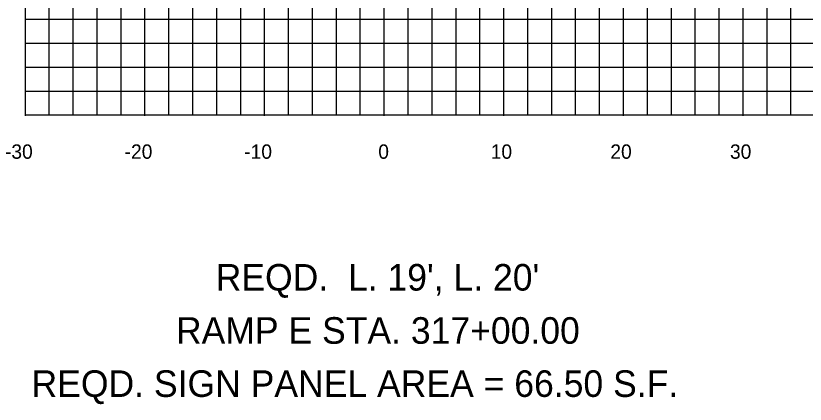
# Model space of a CAD drawing. Extents: x 2193008 to 2198143, y 1236112 to 1237864.
# Drawn here: x 2195238 to 2195304, y 1237233.9 to 1237266.4 of the extents above; entities that cross this region are included whole.
import ezdxf

# ---------------------------------------------------------------- set-up
doc = ezdxf.new("R2010")
doc.units = 0
for name, color, linetype in [('60', 7, 'Continuous'), ('Level 55', 7, 'Continuous'), ('LIMT-CSLINE', 7, 'Continuous'), ('M-ROADS', 7, 'Continuous')]:
    doc.layers.add(name, color=color, linetype=linetype)

msp = doc.modelspace()

# ---------------------------------------------------------------- linework, layer by layer
at = {"layer": '60'}
for p, q in [((2195238.783, 1237258.106), (2195238.783, 1237318.106)), ((2195238.783, 1237258.046), (2195238.783, 1237258.106)), ((2195238.783, 1237258.106), (2195368.783, 1237258.106)), ((2195248.783, 1237258.046), (2195248.783, 1237258.106)), ((2195258.783, 1237258.046), (2195258.783, 1237258.106)), ((2195268.783, 1237258.046), (2195268.783, 1237258.106)), ((2195278.783, 1237258.046), (2195278.783, 1237258.106)), ((2195288.783, 1237258.046), (2195288.783, 1237258.106)), ((2195298.783, 1237258.046), (2195298.783, 1237258.106))]:
    msp.add_line(p, q, dxfattribs=at)
at = {"layer": 'M-ROADS'}
for p, q in [((2195240.783, 1237258.106), (2195240.783, 1237318.106)), ((2195242.783, 1237258.106), (2195242.783, 1237318.106)), ((2195244.783, 1237258.106), (2195244.783, 1237318.106)), ((2195246.783, 1237258.106), (2195246.783, 1237318.106)), ((2195248.783, 1237258.106), (2195248.783, 1237318.106)), ((2195250.783, 1237258.106), (2195250.783, 1237318.106)), ((2195252.783, 1237258.106), (2195252.783, 1237318.106)), ((2195254.783, 1237258.106), (2195254.783, 1237318.106)), ((2195256.783, 1237258.106), (2195256.783, 1237318.106)), ((2195258.783, 1237258.106), (2195258.783, 1237318.106)), ((2195260.783, 1237258.106), (2195260.783, 1237318.106)), ((2195262.783, 1237258.106), (2195262.783, 1237318.106)), ((2195264.783, 1237258.106), (2195264.783, 1237318.106)), ((2195266.783, 1237258.106), (2195266.783, 1237318.106)), ((2195268.783, 1237258.106), (2195268.783, 1237318.106)), ((2195270.783, 1237258.106), (2195270.783, 1237318.106)), ((2195272.783, 1237258.106), (2195272.783, 1237318.106)), ((2195274.783, 1237258.106), (2195274.783, 1237318.106)), ((2195276.783, 1237258.106), (2195276.783, 1237318.106)), ((2195278.783, 1237258.106), (2195278.783, 1237318.106)), ((2195280.783, 1237258.106), (2195280.783, 1237318.106)), ((2195282.783, 1237258.106), (2195282.783, 1237318.106)), ((2195284.783, 1237258.106), (2195284.783, 1237318.106)), ((2195286.783, 1237258.106), (2195286.783, 1237318.106)), ((2195288.783, 1237258.106), (2195288.783, 1237318.106)), ((2195290.783, 1237258.106), (2195290.783, 1237318.106)), ((2195292.783, 1237258.106), (2195292.783, 1237318.106)), ((2195294.783, 1237258.106), (2195294.783, 1237318.106)), ((2195296.783, 1237258.106), (2195296.783, 1237318.106)), ((2195298.783, 1237258.106), (2195298.783, 1237318.106)), ((2195300.783, 1237258.106), (2195300.783, 1237318.106)), ((2195302.783, 1237258.106), (2195302.783, 1237318.106)), ((2195238.783, 1237266.106), (2195368.783, 1237266.106)), ((2195238.783, 1237264.106), (2195368.783, 1237264.106)), ((2195238.783, 1237262.106), (2195368.783, 1237262.106)), ((2195238.783, 1237260.106), (2195368.783, 1237260.106)), ((2195238.783, 1237258.106), (2195368.783, 1237258.106))]:
    msp.add_line(p, q, dxfattribs=at)

# ---------------------------------------------------------------- texts
at = {"layer": 'Level 55'}
for s, p in [(" REQD.  L. 19', L. 20'", (2195253.868, 1237243.431)), ('RAMP E STA. 317+00.00 ', (2195251.371, 1237238.989)), ('REQD. SIGN PANEL AREA = 66.50 S.F.', (2195239.299, 1237234.547))]:
    msp.add_text(s, height=2.22092, dxfattribs=at).set_placement(p)
at = {"layer": 'LIMT-CSLINE'}
for s, p in [('-30', (2195237.08, 1237254.446)), ('-20', (2195247.08, 1237254.446)), ('-10', (2195257.08, 1237254.446)), ('0', (2195268.283, 1237254.446)), ('10', (2195277.683, 1237254.446)), ('20', (2195287.683, 1237254.446)), ('30', (2195297.683, 1237254.446))]:
    msp.add_text(s, height=1.2, dxfattribs=at).set_placement(p)

doc.saveas('drawing.dxf')
